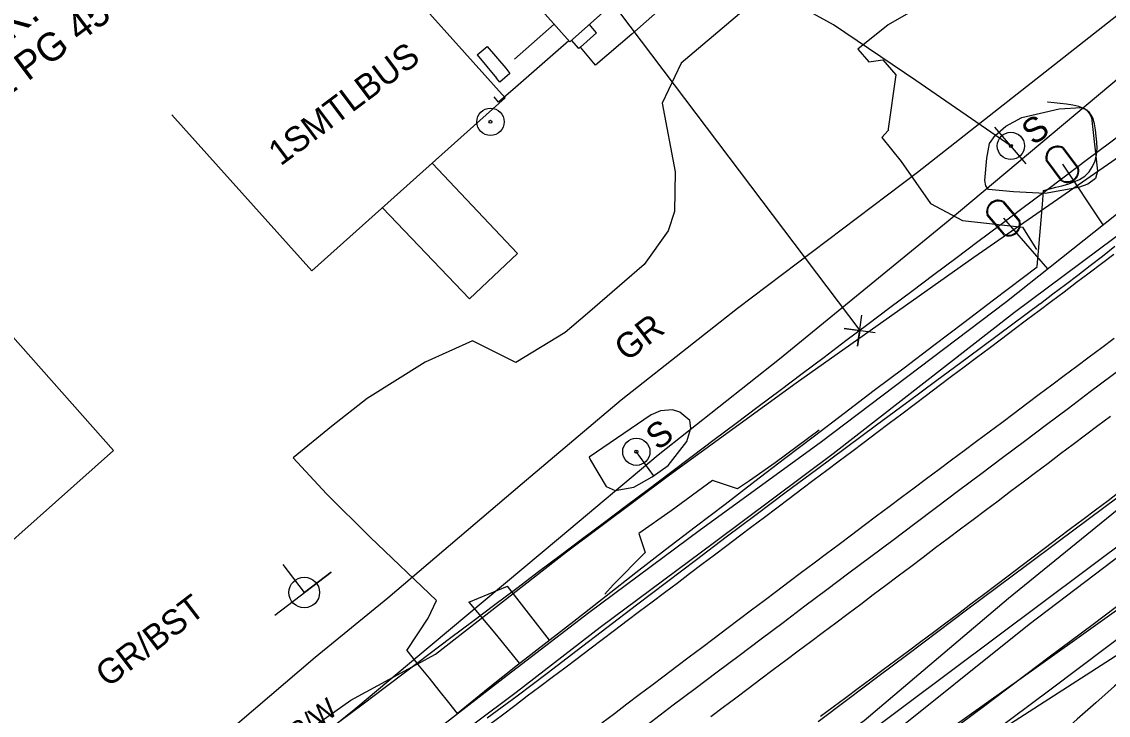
# Model space of a CAD drawing. Extents: x 2186615 to 2188822, y 629899 to 631820.
# Drawn here: x 2186940.8 to 2187114.7, y 630308 to 630418.9 of the extents above; entities that cross this region are included whole.
import ezdxf

# ---------------------------------------------------------------- set-up
doc = ezdxf.new("R2010")
doc.units = 0
for name, color, linetype in [('Exist Building', 7, 'Continuous'), ('Exist Building Metal Canopy', 7, 'Continuous'), ('Exist Building Text', 7, 'Continuous'), ('Exist Environmental Wetland Boundary', 7, 'Continuous'), ('Exist Horizontal Alignment', 7, 'Continuous'), ('Exist Other Culture Area Outline', 7, 'Continuous'), ('Exist Other Culture Fence Line', 7, 'Continuous'), ('Exist Other Culture Located Object CELL', 7, 'Continuous'), ('Exist Other Culture Sign', 7, 'Continuous'), ('Exist Other Culture Sign Post CELL', 7, 'Continuous'), ('Exist Other Culture Sign Post Text', 7, 'Continuous'), ('Exist Property Corner CELL', 7, 'Continuous'), ('Exist Property Deed Book Text', 7, 'Continuous'), ('Exist Property Line', 7, 'Continuous'), ('Exist Property Owner Text', 7, 'Continuous'), ('Exist Right of Way Line', 7, 'Continuous'), ('Exist Right of Way Line Text', 7, 'Continuous'), ('Exist Roads EOP', 7, 'Continuous'), ('Exist Roads EOP Other', 7, 'Continuous'), ('Exist Roads EOP Text', 7, 'Continuous'), ('Exist Roads EOT', 7, 'Continuous'), ('Exist Utilities Gas UG Line SUE LOS B', 7, 'Continuous'), ('Exist Utilities Power Joint Use Telephone CELL', 7, 'Continuous'), ('Exist Utilities Power UG Cable SUE LOS B', 7, 'Continuous'), ('Exist Utilities Sanitary Sewer UG Line', 7, 'Continuous'), ('Exist Utilities Telephone UG Cable SUE LOS C', 7, 'Continuous'), ('Exist Utilities Telephone UG FO SUE LOS B', 7, 'Continuous'), ('Exist Utilities TV UG Cable SUE LOS B', 7, 'Continuous'), ('Exist Utilities TV UG FO Cable SUE LOS B', 7, 'Continuous'), ('Exist Utilities Water Meter CELL', 7, 'Continuous'), ('Exist Utilities Water UG Line SUE LOS B', 7, 'Continuous'), ('Exist Vegetation Woods Line', 7, 'Continuous'), ('Scratch_Level_1', 7, 'Continuous')]:
    doc.layers.add(name, color=color, linetype=linetype)

msp = doc.modelspace()

# ---------------------------------------------------------------- linework, layer by layer
at = {"layer": 'Exist Building'}
for points in [[(2187042.5, 630462.38), (2187059.5, 630443.24), (2187028.51, 630415.7), (2187009.25, 630437.38)], [(2186998.17, 630429.05), (2187018.17, 630406.73), (2186987.25, 630379.03), (2186964.87, 630404.01)], [(2186930.65, 630378.29), (2186955.52, 630350.3), (2186924.68, 630322.9), (2186897.56, 630353.42)]]:
    msp.add_lwpolyline(points, dxfattribs=at)
at = {"layer": 'Exist Building Metal Canopy'}
msp.add_lwpolyline([(2187006.52, 630396.29), (2187020.18, 630381.82), (2187012.5, 630374.59), (2186998.54, 630389.14)], dxfattribs=at)
at = {"layer": 'Exist Environmental Wetland Boundary'}
msp.add_lwpolyline([(2187091.31, 630271.67), (2187085.68, 630287.81), (2187098.27, 630306.17), (2187117.25, 630318.39), (2187145.17, 630331.82), (2187167.38, 630352.86), (2187202.43, 630381.3), (2187228.67, 630401.09), (2187258.21, 630420.52), (2187282.17, 630435.85)], dxfattribs=at)
at = {"layer": 'Exist Horizontal Alignment'}
msp.add_arc((2232330.7, 570095.74), 75342.48, 126.8592631, 127.0730198, dxfattribs=at)
at = {"layer": 'Exist Other Culture Area Outline'}
for points in [[(2187030.23, 630414.83), (2187032.82, 630417.14), (2187031.64, 630418.48)], [(2187013.68, 630413.57), (2187015.29, 630414.95), (2187018.31, 630411.44)], [(2187013.68, 630413.57), (2187016.8, 630409.88)], [(2187018.31, 630411.44), (2187018.94, 630410.6), (2187017.35, 630409.22), (2187016.8, 630409.88)]]:
    msp.add_lwpolyline(points, dxfattribs=at)
at = {"layer": 'Exist Other Culture Fence Line'}
msp.add_line((2187019.69, 630412.88), (2187026.02, 630418.5), dxfattribs=at)
at = {"layer": 'Exist Other Culture Located Object CELL'}
for radius in [2.18, 0.24]:
    msp.add_circle((2187015.83, 630402.88), radius, dxfattribs=at)
at = {"layer": 'Exist Other Culture Sign'}
for p, q in [((2187096.48, 630402.04), (2187101.51, 630396.18)), ((2187039.11, 630350.17), (2187041.87, 630346.32))]:
    msp.add_line(p, q, dxfattribs=at)
at = {"layer": 'Exist Other Culture Sign Post CELL'}
for centre, radius in [((2187099.1, 630399.02), 2.18), ((2187099.1, 630399.02), 0.24), ((2187039.17, 630350.11), 2.18), ((2187039.17, 630350.11), 0.24)]:
    msp.add_circle(centre, radius, dxfattribs=at)
at = {"layer": 'Exist Property Corner CELL'}
msp.add_line((2187074.92, 630369.48), (2187074.92, 630369.48), dxfattribs=at)
msp.add_lwpolyline([(2187077.4, 630369.14), (2187072.45, 630369.83), (2187074.92, 630369.48), (2187074.58, 630367.01), (2187075.27, 630371.96)], dxfattribs=at)
at = {"layer": 'Exist Property Line'}
msp.add_line((2186920.05, 630574.67), (2187074.92, 630369.48), dxfattribs=at)
at = {"layer": 'Exist Right of Way Line'}
for centre, radius, start, end in [((2189028.8, 628141.74), 2893.55, 125.65722, 135.70821), ((2232330.7, 570095.74), 75372.48, 126.8592631, 127.0730198), ((2189028.8, 628141.74), 2763.55, 125.65722, 135.70821), ((2232330.7, 570095.74), 75312.48, 126.8592631, 127.0730198)]:
    msp.add_arc(centre, radius, start, end, dxfattribs=at)
at = {"layer": 'Exist Roads EOP'}
for points in [[(2187104.34, 630391.91), (2187105.31, 630392.16), (2187106.28, 630392.41), (2187107.24, 630392.66), (2187108.21, 630392.93), (2187109.15, 630393.27), (2187110.06, 630393.67), (2187110.92, 630394.18), (2187111.61, 630394.89), (2187112.14, 630395.74), (2187112.56, 630396.64), (2187112.81, 630397.61), (2187112.88, 630398.6), (2187112.85, 630399.6), (2187112.76, 630400.6), (2187112.63, 630401.59), (2187112.46, 630402.57), (2187112.19, 630403.53), (2187111.68, 630404.38), (2187110.88, 630404.97), (2187109.96, 630405.34), (2187108.99, 630405.57), (2187108, 630405.72), (2187107, 630405.82), (2187106.01, 630405.93), (2187105.01, 630406.03), (2187104.95, 630406.04)], [(2187103.31, 630379.72), (2187103.53, 630382.19), (2187103.74, 630384.68), (2187103.96, 630387.17), (2187104.17, 630389.66), (2187104.34, 630391.87)], [(2187103.82, 630373.84), (2187105.81, 630375.34), (2187107.81, 630376.85), (2187109.8, 630378.36), (2187111.78, 630379.88), (2187113.76, 630381.41), (2187115.75, 630382.99)], [(2187010.55, 630308.28), (2187015.47, 630312.28), (2187020.17, 630316.01), (2187024.9, 630319.7), (2187029.63, 630323.39), (2187034.36, 630327.08), (2187039.09, 630330.77), (2187043.82, 630334.46), (2187048.59, 630338.1), (2187053.36, 630341.74), (2187058.13, 630345.38), (2187062.9, 630349.02), (2187067.67, 630352.66), (2187072.44, 630356.3), (2187077.21, 630359.93), (2187082, 630363.55), (2187086.78, 630367.17), (2187091.56, 630370.79), (2187096.34, 630374.41), (2187101.13, 630378.03), (2187103.31, 630379.68)], [(2187015.3, 630307.52), (2187020.13, 630311.08), (2187024.91, 630314.71), (2187029.68, 630318.35), (2187034.44, 630321.99), (2187039.21, 630325.63), (2187043.99, 630329.25), (2187048.78, 630332.87), (2187053.57, 630336.48), (2187058.37, 630340.08), (2187063.17, 630343.68), (2187067.98, 630347.27), (2187072.8, 630350.85), (2187077.61, 630354.42), (2187082.44, 630357.99), (2187087.26, 630361.56), (2187092.09, 630365.13), (2187096.91, 630368.7), (2187101.72, 630372.28), (2187103.8, 630373.83)], [(2187116.26, 630342.84), (2187111.45, 630339.26), (2187106.64, 630335.67), (2187101.83, 630332.08), (2187097.02, 630328.5), (2187092.22, 630324.91), (2187087.41, 630321.31), (2187082.62, 630317.7), (2187077.83, 630314.1), (2187073.03, 630310.49), (2187068.24, 630306.88)], [(2187002.47, 630318.31), (2187004.45, 630315.82), (2187006.01, 630313.87), (2187007.56, 630311.91), (2187009.11, 630309.97), (2187010.49, 630308.23)]]:
    msp.add_lwpolyline(points, dxfattribs=at)
at = {"layer": 'Exist Roads EOP Other'}
for points in [[(2187062.91, 630438.69), (2187051.24, 630428.27), (2187038.44, 630416.92), (2187032.62, 630411.94), (2187030.23, 630414.83), (2187029.95, 630414.61)], [(2187079.81, 630435.28), (2187072.37, 630434.64), (2187064.33, 630427.53), (2187046.36, 630412.28), (2187043.32, 630405.89), (2187045.41, 630394.88), (2187045.29, 630388.53), (2187044.29, 630385.44), (2187040.43, 630380.05)], [(2187086.08, 630422.18), (2187079.44, 630418.41), (2187074.6, 630414.49), (2187076.35, 630412.47), (2187078.6, 630412.78), (2187080.68, 630410.41), (2187079.48, 630401.77), (2187079.48, 630401.5)], [(2187028.37, 630415.86), (2187019.83, 630408.38), (2187017.13, 630406.01), (2187016.43, 630406.87)], [(2187029.95, 630414.61), (2187028.81, 630415.96)], [(2187111.98, 630403.58), (2187112.96, 630394.98), (2187112.61, 630393.81), (2187111.41, 630392.9), (2187109.91, 630392.4), (2187104.57, 630391.42), (2187099.5, 630391.68), (2187095.54, 630392.08), (2187095.08, 630392.65), (2187094.95, 630393.51), (2187095.26, 630397.09), (2187095.7, 630399.4), (2187096.6, 630400.69), (2187098.31, 630402.19), (2187100.86, 630403.59), (2187106.8, 630404.96), (2187110.39, 630405.19), (2187111.19, 630404.78), (2187111.69, 630404.18), (2187111.98, 630403.58)], [(2187079.48, 630401.5), (2187078.43, 630400.37), (2187081.54, 630396.52), (2187086.22, 630389.79), (2187091.37, 630387.1), (2187100.96, 630386.03), (2187103.17, 630382.48)], [(2187040.43, 630380.05), (2187031.38, 630372.21), (2187027.77, 630369.19), (2187019.9, 630364.39), (2187012.95, 630367.86), (2187005.39, 630364.44), (2186996.13, 630358.61)], [(2186996.13, 630358.61), (2186990.38, 630354.12), (2186984.24, 630349.14)], [(2187038.79, 630344.42), (2187041.73, 630346.12), (2187044.25, 630347.93), (2187047.26, 630351.73), (2187047.89, 630353.88), (2187047.72, 630355.09), (2187046.15, 630356.46), (2187044.94, 630356.83), (2187043.04, 630356.66), (2187041.55, 630356), (2187031.65, 630349.25), (2187031.83, 630348.77)], [(2187068.43, 630353.54), (2187061.38, 630348.34), (2187057.27, 630345.44), (2187055.38, 630344.2), (2187051.38, 630345.52), (2187044.76, 630340.66), (2187039.56, 630337.05), (2187040.56, 630334.01), (2187035.48, 630328.84), (2187034.11, 630327.34)], [(2186984.24, 630349.14), (2186989.61, 630343.35), (2186996.59, 630336.43), (2187007.21, 630326.3)], [(2187031.83, 630348.77), (2187034.35, 630344.54), (2187035.8, 630343.93), (2187038.79, 630344.42)], [(2187012.35, 630326.06), (2187018.54, 630328.62)], [(2187025.3, 630319.95), (2187018.54, 630328.62)], [(2187002.47, 630318.31), (2187005.85, 630323.49), (2187007.21, 630326.3)], [(2187012.35, 630326.06), (2187016.82, 630320.75), (2187020.4, 630316.3)]]:
    msp.add_lwpolyline(points, dxfattribs=at)
at = {"layer": 'Exist Roads EOT'}
for points in [[(2187015.75, 630306.52), (2187017.74, 630308.03), (2187019.74, 630309.54), (2187021.73, 630311.04), (2187023.73, 630312.55), (2187025.72, 630314.05), (2187027.72, 630315.56), (2187029.71, 630317.06), (2187031.71, 630318.57), (2187033.7, 630320.08), (2187035.7, 630321.58), (2187037.69, 630323.09), (2187039.69, 630324.59), (2187041.68, 630326.1), (2187043.68, 630327.6), (2187045.68, 630329.11), (2187047.67, 630330.61), (2187049.67, 630332.12), (2187051.67, 630333.62), (2187053.66, 630335.12), (2187055.66, 630336.63), (2187057.66, 630338.13), (2187059.66, 630339.64), (2187061.65, 630341.14), (2187063.65, 630342.64), (2187065.65, 630344.15), (2187067.64, 630345.65), (2187069.64, 630347.15), (2187071.64, 630348.66), (2187073.64, 630350.16), (2187075.63, 630351.66), (2187077.63, 630353.17), (2187079.63, 630354.67), (2187081.63, 630356.17), (2187083.63, 630357.67), (2187085.62, 630359.17), (2187087.62, 630360.68), (2187089.62, 630362.18), (2187091.62, 630363.68), (2187093.62, 630365.18), (2187095.62, 630366.68), (2187097.61, 630368.19), (2187099.61, 630369.69), (2187101.61, 630371.19), (2187103.61, 630372.7), (2187105.6, 630374.2), (2187107.6, 630375.7), (2187109.6, 630377.21), (2187111.6, 630378.71), (2187113.59, 630380.22), (2187115.59, 630381.72)], [(2187033.67, 630306.75), (2187035.66, 630308.26), (2187037.66, 630309.77), (2187039.65, 630311.27), (2187041.65, 630312.78), (2187043.65, 630314.28), (2187045.64, 630315.79), (2187047.64, 630317.29), (2187049.63, 630318.8), (2187051.63, 630320.3), (2187053.63, 630321.81), (2187055.62, 630323.31), (2187057.62, 630324.82), (2187059.61, 630326.32), (2187061.61, 630327.83), (2187063.61, 630329.33), (2187065.6, 630330.84), (2187067.6, 630332.34), (2187069.6, 630333.84), (2187071.6, 630335.34), (2187073.6, 630336.84), (2187075.6, 630338.34), (2187077.6, 630339.83), (2187079.61, 630341.33), (2187081.61, 630342.83), (2187083.61, 630344.33), (2187085.61, 630345.82), (2187087.61, 630347.32), (2187089.62, 630348.82), (2187091.62, 630350.31), (2187093.62, 630351.81), (2187095.62, 630353.31), (2187097.63, 630354.8), (2187099.63, 630356.3), (2187101.63, 630357.8), (2187103.63, 630359.3), (2187105.63, 630360.8), (2187107.63, 630362.3), (2187109.63, 630363.8), (2187111.63, 630365.3), (2187113.63, 630366.8), (2187115.63, 630368.3)], [(2187051.07, 630307.76), (2187053.07, 630309.26), (2187055.07, 630310.76), (2187057.07, 630312.26), (2187059.07, 630313.76), (2187061.08, 630315.25), (2187063.08, 630316.75), (2187065.08, 630318.25), (2187067.08, 630319.75), (2187069.08, 630321.25), (2187071.08, 630322.75), (2187073.08, 630324.25), (2187075.08, 630325.75), (2187077.08, 630327.25), (2187079.07, 630328.75), (2187081.07, 630330.26), (2187083.07, 630331.76), (2187085.07, 630333.26), (2187087.06, 630334.77), (2187089.06, 630336.27), (2187091.06, 630337.77), (2187093.06, 630339.28), (2187095.05, 630340.78), (2187097.05, 630342.28), (2187099.05, 630343.79), (2187101.05, 630345.29), (2187103.04, 630346.79), (2187105.04, 630348.3), (2187107.04, 630349.8), (2187109.04, 630351.3), (2187111.03, 630352.81), (2187113.03, 630354.31), (2187115.03, 630355.81)], [(2187116.63, 630343.79), (2187114.64, 630342.28), (2187112.64, 630340.78), (2187110.64, 630339.27), (2187108.65, 630337.77), (2187106.66, 630336.26), (2187104.66, 630334.75), (2187102.67, 630333.24), (2187100.67, 630331.74), (2187098.68, 630330.23), (2187096.68, 630328.72), (2187094.69, 630327.22), (2187092.7, 630325.71), (2187090.7, 630324.2), (2187088.7, 630322.7), (2187086.7, 630321.2), (2187084.69, 630319.71), (2187082.69, 630318.21), (2187080.69, 630316.72), (2187078.69, 630315.22), (2187076.68, 630313.72), (2187074.68, 630312.23), (2187072.67, 630310.74), (2187070.67, 630309.24), (2187068.66, 630307.75)]]:
    msp.add_lwpolyline(points, dxfattribs=at)
at = {"layer": 'Exist Utilities Gas UG Line SUE LOS B'}
msp.add_lwpolyline([(2186961.34, 630266.71), (2186999.6, 630296.45), (2187019.95, 630311.63), (2187033.4, 630322.07), (2187051.7, 630335.62), (2187070.69, 630349.82), (2187099.69, 630372.44), (2187126.47, 630392.39)], dxfattribs=at)
at = {"layer": 'Exist Utilities Power Joint Use Telephone CELL'}
msp.add_line((2186986.04, 630327.59), (2186986.04, 630327.59), dxfattribs=at)
msp.add_lwpolyline([(2186981.32, 630323.99), (2186990.36, 630330.83), (2186986.06, 630327.57), (2186982.64, 630332.07)], dxfattribs=at)
msp.add_circle((2186986.04, 630327.59), 2.45, dxfattribs=at)
at = {"layer": 'Exist Utilities Power UG Cable SUE LOS B'}
msp.add_lwpolyline([(2187099.12, 630398.98), (2187083.88, 630409.5), (2187070.7, 630418.39), (2187052.85, 630428.25)], dxfattribs=at)
at = {"layer": 'Exist Utilities Sanitary Sewer UG Line'}
msp.add_line((2186953.53, 630213.34), (2187280.26, 630457.75), dxfattribs=at)
at = {"layer": 'Exist Utilities Telephone UG Cable SUE LOS C'}
msp.add_lwpolyline([(2187048.71, 630267.56), (2187045.35, 630278.25), (2187057.02, 630287.25), (2187078.19, 630303.42), (2187102.04, 630322.51), (2187119.95, 630336.14), (2187137.94, 630349.88), (2187161.71, 630367.86), (2187186.02, 630384.64), (2187207.08, 630401.8), (2187231.6, 630419.79), (2187256.85, 630438.71), (2187278.85, 630453.8), (2187296.98, 630467.54), (2187304.94, 630472.73), (2187317.62, 630478.55), (2187327.51, 630484.53), (2187332.68, 630485.86), (2187337.99, 630482.8), (2187346.28, 630476.8)], dxfattribs=at)
at = {"layer": 'Exist Utilities Telephone UG FO SUE LOS B'}
for points in [[(2187049.38, 630270.15), (2187042.5, 630278.37), (2187044.06, 630284.34), (2187057.31, 630294.02), (2187075.64, 630307.12), (2187098.73, 630326.67), (2187116.95, 630341.49), (2187134.44, 630355.42), (2187157.81, 630373.05), (2187181.9, 630390.79), (2187205.12, 630408.7), (2187231.97, 630429.32), (2187252.44, 630444.7), (2187272.54, 630459.69), (2187294.09, 630476.32), (2187309.64, 630487.97), (2187327.19, 630501.03), (2187332.67, 630500.22), (2187340.34, 630491.39), (2187346.28, 630476.8)], [(2186916.21, 630248.6), (2186927.38, 630260.09), (2186942.37, 630270.68), (2186955.34, 630280.32), (2186974.86, 630297.18), (2186993.47, 630310.39), (2187007.03, 630317.72), (2187028, 630334.1), (2187044.5, 630346.39), (2187064.77, 630361.14), (2187093.15, 630381.24), (2187121.86, 630401.1)]]:
    msp.add_lwpolyline(points, dxfattribs=at)
at = {"layer": 'Exist Utilities TV UG Cable SUE LOS B'}
msp.add_lwpolyline([(2187009.04, 630243.54), (2187005.06, 630241.81), (2186997.15, 630243.52), (2186988.34, 630246.09), (2186958.26, 630264.28), (2186948.02, 630270.76), (2186941.05, 630277.35), (2186953.05, 630286.67), (2186970.62, 630302.57), (2186987.79, 630317.23), (2186999.43, 630326.74), (2187020.89, 630345.03), (2187036.72, 630358.42), (2187055.34, 630373.05), (2187084.13, 630394.81), (2187116.07, 630419.88)], dxfattribs=at)
at = {"layer": 'Exist Utilities TV UG FO Cable SUE LOS B'}
msp.add_lwpolyline([(2186956.68, 630278.76), (2186994.31, 630309.11), (2187006.19, 630319.06), (2187027.03, 630336.52), (2187042.65, 630349.62), (2187062.09, 630364.95), (2187089.07, 630387.06), (2187116.73, 630410.24)], dxfattribs=at)
at = {"layer": 'Exist Utilities Water Meter CELL'}
for p, q in [((2187107.34, 630396.09), (2187107.34, 630396.09)), ((2187097.93, 630387.49), (2187097.93, 630387.49))]:
    msp.add_line(p, q, dxfattribs=at)
for points in [[(2187107.37, 630398.65), (2187109.81, 630395.39)], [(2187107.48, 630398.74), (2187109.92, 630395.47)], [(2187107.19, 630393.44), (2187104.74, 630396.72)], [(2187107.3, 630393.52), (2187104.85, 630396.81)], [(2187097.8, 630390.05), (2187100.44, 630386.95)], [(2187097.9, 630390.14), (2187100.54, 630387.04)], [(2187097.95, 630384.84), (2187095.3, 630387.96)], [(2187098.05, 630384.93), (2187095.4, 630388.05)]]:
    msp.add_lwpolyline(points, dxfattribs=at)
for centre, radius, start, end in [((2187106.55, 630397.13), 1.86, 59.8616, 192.663), ((2187106.56, 630397.12), 1.73, 61.9845, 190.4659), ((2187108.11, 630395.05), 1.86, 240.3319, 12.992), ((2187108.12, 630395.04), 1.73, 241.8108, 11.5564), ((2187097.08, 630388.48), 1.86, 63.4723, 196.2737), ((2187097.08, 630388.47), 1.73, 65.5952, 194.0766), ((2187098.76, 630386.5), 1.86, 243.9426, 16.6026), ((2187098.77, 630386.49), 1.73, 245.4214, 15.1671)]:
    msp.add_arc(centre, radius, start, end, dxfattribs=at)
at = {"layer": 'Exist Utilities Water UG Line SUE LOS B'}
for p, q in [((2187107.34, 630396.09), (2187113.81, 630386.38)), ((2187097.93, 630387.49), (2187104.98, 630379.37))]:
    msp.add_line(p, q, dxfattribs=at)
msp.add_lwpolyline([(2186959.77, 630269.32), (2186998.9, 630299.18), (2187017.82, 630313.83), (2187031.57, 630324.4), (2187049.45, 630337.67), (2187068.61, 630351.56), (2187098.38, 630374.13), (2187124.77, 630395.09)], dxfattribs=at)
at = {"layer": 'Exist Vegetation Woods Line'}
for points in [[(2187230.5, 630408.89), (2187277.27, 630443.25), (2187318.86, 630473.26), (2187330.63, 630477.31), (2187307.15, 630458.86), (2187234.21, 630405.64), (2187193, 630375.63), (2187170.08, 630359.23), (2187132.55, 630332.44), (2187105.52, 630312.12)], [(2187103.49, 630315.88), (2187138.52, 630340.83), (2187186.53, 630376), (2187214.46, 630397), (2187230.5, 630408.89)], [(2187105.52, 630312.12), (2187053.92, 630273.62), (2187052.39, 630274.33), (2187051.38, 630275.58), (2187053.56, 630278.83), (2187078.95, 630298.35), (2187103.49, 630315.88)]]:
    msp.add_lwpolyline(points, dxfattribs=at)
at = {"layer": 'Scratch_Level_1'}
msp.add_arc((2189028.8, 628141.74), 2815.55, 125.65722, 135.70821, dxfattribs=at)

# ---------------------------------------------------------------- texts
at = {"layer": 'Exist Building Text'}
msp.add_text('1SMTLBUS', height=4, rotation=36.8593, dxfattribs=at).set_placement((2186982.25, 630395.72))
at = {"layer": 'Exist Other Culture Sign Post Text'}
for p in [(2187102.74, 630398.99), (2187042.62, 630350.21)]:
    msp.add_text('S', height=4, rotation=36.8593, dxfattribs=at).set_placement(p)
at = {"layer": 'Exist Property Deed Book Text'}
msp.add_text('DB 1952 PG 458', height=4.5, rotation=36.8593, dxfattribs=at).set_placement((2186921.73, 630394.23))
at = {"layer": 'Exist Property Owner Text'}
msp.add_text('JOHANNA K. PARKER', height=5, rotation=36.8593, dxfattribs=at).set_placement((2186911.95, 630395.49))
at = {"layer": 'Exist Right of Way Line Text'}
msp.add_text('EXISTING R/W', height=3.2, rotation=36.9046, dxfattribs=at).set_placement((2186968.02, 630290.64))
at = {"layer": 'Exist Roads EOP Text'}
for s, p in [('GR', (2187037.63, 630364.42)), ('GR/BST', (2186954.62, 630312.28))]:
    msp.add_text(s, height=4, rotation=37.422, dxfattribs=at).set_placement(p)

doc.saveas('drawing.dxf')
